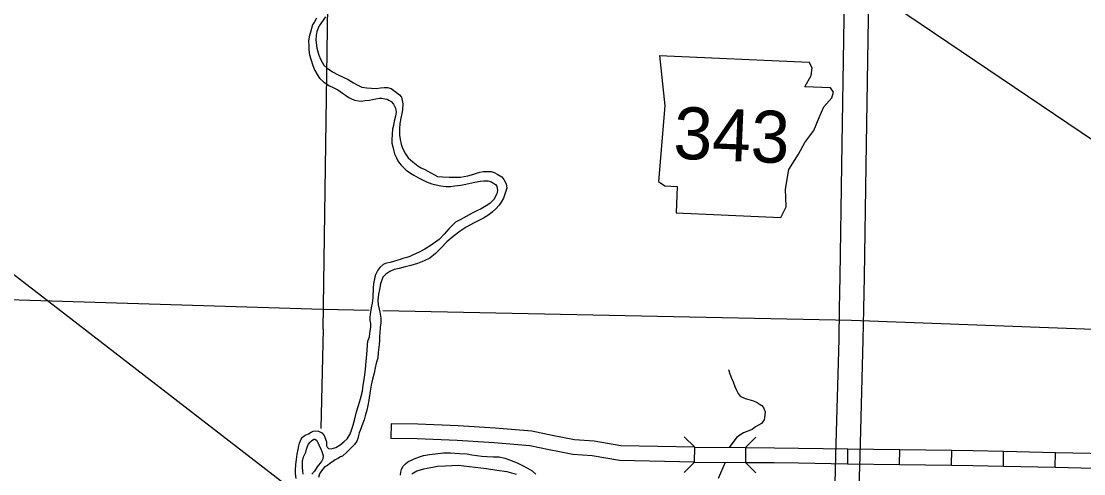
# Model space of a CAD drawing. Extents: x 1196286 to 1268366, y 2040822 to 2082115.
# Drawn here: x 1235560 to 1239613, y 2058686 to 2060409 of the extents above; entities that cross this region are included whole.
import ezdxf

# ---------------------------------------------------------------- set-up
doc = ezdxf.new("R2010")
doc.units = 0
for name, color, linetype in [('60', 7, 'Continuous'), ('61', 7, 'Continuous'), ('62', 7, 'Continuous'), ('Level 69', 7, 'Continuous'), ('Level 72', 7, 'Continuous'), ('Level 78', 7, 'Continuous'), ('Level 8', 7, 'Continuous'), ('Level 83', 7, 'Continuous'), ('Level 87', 7, 'Continuous')]:
    doc.layers.add(name, color=color, linetype=linetype)

msp = doc.modelspace()

# ---------------------------------------------------------------- linework, layer by layer
at = {"layer": '60'}
for points in [[(1236711.8, 2059236.7), (1236740.6, 2061264.4), (1236742.7, 2061422.9)], [(1234763.8, 2059372.9), (1236710.8, 2059312.7), (1236887.6, 2059309.1)], [(1236939.7, 2059308), (1238726.7, 2059270.7), (1239786.4, 2059231.7), (1240836.4, 2059202.8)], [(1236711.8, 2059236.7), (1236702.7, 2058857.5)]]:
    msp.add_lwpolyline(points, dxfattribs=at)
at = {"layer": '61'}
for p, q in [((1238712.6, 2058723.8), (1238713.3, 2058780)), ((1238910.6, 2058721.2), (1238911.3, 2058777.5)), ((1239108.6, 2058718.7), (1239109.3, 2058774.9)), ((1239306.3, 2058715), (1239307.5, 2058771.3)), ((1239504.2, 2058710.7), (1239505.5, 2058766.9))]:
    msp.add_line(p, q, dxfattribs=at)
for points in [[(1238713.3, 2058780), (1238911.3, 2058777.5)], [(1238911.3, 2058777.5), (1239109.3, 2058774.9)], [(1239109.3, 2058774.9), (1239190.8, 2058773.8), (1239307.5, 2058771.3)], [(1239307.5, 2058771.3), (1239505.5, 2058766.9)], [(1239505.5, 2058766.9), (1239703.4, 2058762.5)], [(1238712.6, 2058723.8), (1238910.6, 2058721.2)], [(1238910.6, 2058721.2), (1239108.6, 2058718.7)], [(1239108.6, 2058718.7), (1239189.8, 2058717.6), (1239306.3, 2058715)], [(1239306.3, 2058715), (1239504.2, 2058710.7)], [(1239504.2, 2058710.7), (1239702.2, 2058706.3)]]:
    msp.add_lwpolyline(points, dxfattribs=at)
at = {"layer": '62'}
for points in [[(1236687, 2060421.2), (1236678.6, 2060407.4), (1236671.8, 2060395.4), (1236667.1, 2060381.6), (1236663.6, 2060367.7)], [(1236720.4, 2060426.5), (1236697.2, 2060392.1), (1236692.2, 2060383.2), (1236687.2, 2060370.4), (1236684.8, 2060355.4), (1236684.2, 2060337.7), (1236686.6, 2060317.8), (1236688, 2060306.8), (1236694.8, 2060280.1)], [(1236663.6, 2060367.7), (1236658.9, 2060350), (1236656.5, 2060333.9), (1236657.4, 2060315.8), (1236657.6, 2060300), (1236659.3, 2060281.2), (1236664.3, 2060265), (1236672.3, 2060240.4), (1236680.3, 2060222.3), (1236688.8, 2060206), (1236697.3, 2060193.1), (1236714.3, 2060177.2), (1236735.9, 2060163.8), (1236750.1, 2060156.5), (1236767.6, 2060147.6), (1236785.8, 2060135.4), (1236797.7, 2060127.4), (1236810, 2060118.9), (1236822.3, 2060112.4), (1236832.3, 2060108.9), (1236846.6, 2060106.1), (1236857.4, 2060105.6), (1236870.9, 2060107.4), (1236888.9, 2060109.1), (1236900.2, 2060111.6), (1236913.3, 2060114.1), (1236927.2, 2060116.9), (1236936.2, 2060116.8), (1236947.1, 2060114.5), (1236955.7, 2060112.1), (1236962.8, 2060109), (1236971.7, 2060103.7), (1236980.6, 2060093.8), (1236987.9, 2060077.9), (1236990.7, 2060062.8), (1236987.6, 2060047.4), (1236982.9, 2060029.4), (1236979.7, 2060012.2), (1236976.1, 2059998.3), (1236973.8, 2059959.2), (1236974.4, 2059944.9), (1236977.3, 2059930.9), (1236981.6, 2059915.1), (1236984.5, 2059904.5), (1236991, 2059888.6), (1236996.5, 2059877.7), (1237003.2, 2059868.2), (1237009.1, 2059860.6), (1237018, 2059851.9), (1237029.1, 2059842), (1237045.1, 2059830.5), (1237057.4, 2059822.9), (1237075.3, 2059812.9), (1237090.9, 2059804.8), (1237106.2, 2059797.9), (1237126.7, 2059789.8), (1237142.8, 2059786.6), (1237160.4, 2059783), (1237180.2, 2059780.5), (1237197.1, 2059780), (1237214.3, 2059782.4), (1237237.2, 2059785.6), (1237256, 2059788.7), (1237272.5, 2059793.1), (1237290.9, 2059796.6), (1237311.6, 2059800.2), (1237324.7, 2059801.9), (1237340.5, 2059801), (1237354.6, 2059797.1), (1237368.8, 2059787.5), (1237374.7, 2059781.1), (1237377.1, 2059764.1), (1237374.8, 2059752.1), (1237363.3, 2059730), (1237348.1, 2059714.8), (1237333.8, 2059706.3), (1237314.2, 2059694.4), (1237298, 2059687.5), (1237279.9, 2059678.6), (1237256.9, 2059666.1), (1237233.9, 2059653.5), (1237216.6, 2059644), (1237191.2, 2059618.6), (1237173.7, 2059597.8), (1237154.4, 2059578), (1237123.8, 2059556.9), (1237099.3, 2059541.4), (1237075.1, 2059528.5), (1237055.2, 2059519.3), (1237042.4, 2059513.8), (1237031.5, 2059509.8), (1237015.7, 2059505.1), (1237005.9, 2059501.8), (1236996.1, 2059499.3), (1236979.6, 2059494.2), (1236967.2, 2059490.9), (1236952.9, 2059488.1), (1236941.2, 2059482.9), (1236928.4, 2059471.4), (1236920.4, 2059460.9), (1236909.7, 2059441.1)], [(1236694.8, 2060280.1), (1236701.4, 2060264.9), (1236707.7, 2060253.2), (1236714.7, 2060241.9), (1236726.9, 2060230.4), (1236747.7, 2060217), (1236769, 2060205.9), (1236788.7, 2060197), (1236807, 2060187.1), (1236828.2, 2060175.2), (1236841.6, 2060166.8), (1236859.5, 2060158.7), (1236878.2, 2060155.8), (1236913.8, 2060153.2), (1236930.3, 2060155.3), (1236944.9, 2060157), (1236957.3, 2060157.2), (1236970.7, 2060153.7), (1236991.6, 2060138.4), (1237003.4, 2060128.9), (1237010.1, 2060120.5), (1237013.7, 2060107.3), (1237015.4, 2060094.9), (1237014.4, 2060072.3), (1237012.4, 2060057.7), (1237008.5, 2060039.7), (1237004.9, 2060020.5), (1237003.1, 2059999.9), (1237003.3, 2059975.8), (1237005.3, 2059958.5), (1237009.6, 2059940.7), (1237014.7, 2059926), (1237025.7, 2059904.1), (1237036, 2059889.3), (1237053.5, 2059873.7), (1237073.2, 2059858.4), (1237086.2, 2059851.5), (1237099.6, 2059844.6), (1237148, 2059817.7), (1237166.8, 2059817.2), (1237192.2, 2059816.1), (1237217.3, 2059815.5), (1237235.7, 2059815.3), (1237263.5, 2059820.3), (1237286.4, 2059827.2), (1237296.6, 2059830.4), (1237309.3, 2059834.4), (1237323.6, 2059836.5), (1237352.1, 2059837.7), (1237364.4, 2059833.5), (1237378.6, 2059826.2), (1237393.1, 2059816.6), (1237401.6, 2059807.1), (1237409.7, 2059790.1), (1237412.9, 2059774.2), (1237400.1, 2059734.9), (1237390.9, 2059719.9), (1237383.7, 2059708.7), (1237370.4, 2059694.6), (1237357.9, 2059683.4), (1237343.5, 2059672.3), (1237323.2, 2059659.7), (1237308.4, 2059651.6), (1237287.7, 2059640.9), (1237257.9, 2059624.7), (1237234.9, 2059609.5), (1237207.3, 2059589.5), (1237183.5, 2059568.7), (1237160.7, 2059544.5), (1237141, 2059524.8), (1237119.1, 2059507.3), (1237097.6, 2059496.7), (1237071.7, 2059486.8), (1237046.8, 2059478.4), (1237025.1, 2059473.4), (1237002.1, 2059468), (1236983, 2059463.3), (1236965.7, 2059456.7), (1236950.6, 2059446), (1236939.9, 2059434), (1236930.3, 2059409.3), (1236926.3, 2059387.2), (1236923.1, 2059369.9), (1236920.6, 2059348.5), (1236921.5, 2059329.3), (1236925.1, 2059312.7), (1236927.6, 2059301.7), (1236931.5, 2059278.4), (1236931.6, 2059259.6), (1236928.8, 2059243.8), (1236928.2, 2059221.6), (1236927.4, 2059211.1), (1236926.6, 2059194.9), (1236925.5, 2059178)], [(1236909.7, 2059441.1), (1236906.4, 2059422), (1236904.4, 2059408.8), (1236902, 2059394.6), (1236900.8, 2059355.5), (1236898.8, 2059335.9), (1236896.7, 2059323.9), (1236894, 2059310.4), (1236891.2, 2059292.4), (1236890.3, 2059281.8), (1236890.5, 2059269.4), (1236891.9, 2059258.1), (1236892.9, 2059247.2), (1236891.6, 2059234.8), (1236888.9, 2059221.7), (1236887.2, 2059206.6), (1236882.6, 2059191.8)], [(1236608.4, 2058667), (1236606.2, 2058687), (1236606, 2058699.4), (1236607.2, 2058720.8), (1236609.8, 2058740.3), (1236613.2, 2058760.9), (1236616.2, 2058778.6), (1236619.1, 2058791.7), (1236621.6, 2058802.5), (1236628.6, 2058817.8), (1236632.9, 2058824.5), (1236643.2, 2058832.9), (1236655.6, 2058837.6), (1236665.9, 2058843.8), (1236674.2, 2058847.4), (1236682.1, 2058849.5), (1236693.7, 2058848.1), (1236707, 2058841.4), (1236716.2, 2058831.1), (1236724, 2058807.2), (1236725.2, 2058791.4), (1236727.3, 2058786.9), (1236732.8, 2058781.5), (1236742.2, 2058780.2), (1236759.9, 2058785.5), (1236776.6, 2058795.3), (1236790.7, 2058806.7), (1236803.3, 2058819.2), (1236814.1, 2058835.5), (1236818.1, 2058847.9), (1236826, 2058870.6), (1236832.5, 2058895), (1236839, 2058921.9), (1236846.6, 2058946.2), (1236854.6, 2058971.6), (1236861.6, 2059000.8), (1236864.3, 2059023.4), (1236869, 2059052.2), (1236873, 2059084.1), (1236876.2, 2059113.4), (1236879, 2059140.4), (1236882.6, 2059191.8)], [(1236925.5, 2059178), (1236921.9, 2059147.2), (1236920.3, 2059126.4), (1236914.3, 2059107), (1236910.2, 2059088.6), (1236906, 2059068.8), (1236900.7, 2059046.3), (1236895, 2059023.1), (1236891.6, 2059000.6), (1236886, 2058965.4), (1236882.2, 2058945.5), (1236878.1, 2058927.9), (1236872.1, 2058906.6), (1236868, 2058890.9), (1236863.3, 2058878.5), (1236858.2, 2058864.7), (1236852.6, 2058850.5), (1236848.7, 2058841.6), (1236846.6, 2058831.1), (1236843.8, 2058820.3), (1236840.2, 2058809.8), (1236831.7, 2058797.2), (1236814.5, 2058780.2), (1236802.3, 2058768.4), (1236785.1, 2058753), (1236777.6, 2058750.5), (1236768.1, 2058744.3), (1236757.8, 2058738.1), (1236748, 2058731.5), (1236737.7, 2058724.6), (1236728.6, 2058717.2), (1236726.3, 2058715.8), (1236720.2, 2058712.9), (1236716, 2058709.6), (1236705.3, 2058697), (1236698.3, 2058685.9), (1236693.6, 2058671.3)], [(1238258.1, 2059082.3), (1238263.1, 2059066), (1238269.5, 2059049.7), (1238276.3, 2059035.3), (1238281.6, 2059018.2), (1238288.1, 2059003.8), (1238294.6, 2058990.9), (1238302.2, 2058981), (1238321.2, 2058971.9), (1238336.1, 2058969), (1238353.3, 2058963.8), (1238367, 2058956.7), (1238378.8, 2058950.1), (1238385.1, 2058945.8), (1238392.1, 2058938.5), (1238394.6, 2058930.6), (1238397.4, 2058922.6), (1238396.4, 2058908.7), (1238394.2, 2058891.1), (1238383.5, 2058877.7), (1238361.2, 2058865), (1238348.1, 2058854.2), (1238315.3, 2058841.3), (1238289.4, 2058825), (1238259.9, 2058785.6)], [(1236645.7, 2058767.7), (1236648.5, 2058779.4), (1236655.2, 2058797.3), (1236661.7, 2058805.5), (1236667.5, 2058811.4), (1236676.6, 2058817.2), (1236680.3, 2058817.5), (1236686.6, 2058813.3), (1236692.4, 2058802.2), (1236698.1, 2058789.3), (1236702.5, 2058781), (1236707.1, 2058770.7), (1236709.6, 2058762.8), (1236711.3, 2058754.1), (1236710.7, 2058742.8), (1236706, 2058732.4), (1236689.5, 2058712.4), (1236678.7, 2058696), (1236668.7, 2058683.5)], [(1236635.7, 2058684.5), (1236634.1, 2058696.9), (1236633.2, 2058708.2), (1236633.1, 2058719.9), (1236633.7, 2058734.2), (1236637.3, 2058750.7), (1236645.7, 2058767.7)], [(1237006.7, 2058680.1), (1237008.4, 2058692.1), (1237010.5, 2058701.4), (1237016, 2058713.7), (1237025.5, 2058723.3), (1237035.4, 2058730.6), (1237059.6, 2058743), (1237079.3, 2058750.5), (1237095.1, 2058755.8), (1237117.7, 2058758.7), (1237170.3, 2058765.6), (1237197.2, 2058765), (1237232.4, 2058762.8), (1237261.6, 2058761.8), (1237278.4, 2058758.1), (1237317.3, 2058752.8), (1237337.9, 2058751.3), (1237360.7, 2058750.5), (1237383.2, 2058749.6), (1237405.2, 2058745), (1237426.8, 2058737.5), (1237454.3, 2058726.4), (1237472.5, 2058717.7), (1237491.4, 2058706.8), (1237508.8, 2058697.1), (1237523.6, 2058684.7)], [(1237449, 2058682.5), (1237414.3, 2058693), (1237374.3, 2058697.9), (1237335.1, 2058704.7), (1237227.4, 2058717), (1237179, 2058715), (1237147.5, 2058713), (1237123, 2058708.2), (1237095.2, 2058703.5), (1237068.8, 2058696.1), (1237049.9, 2058684.5)], [(1238245.7, 2058728.3), (1238218.5, 2058667.8)]]:
    msp.add_lwpolyline(points, dxfattribs=at)
at = {"layer": 'Level 69'}
for p, q in [((1238128.6, 2058730.2), (1238129, 2058786.5)), ((1238322.7, 2058785.4), (1238322.4, 2058729.1))]:
    msp.add_line(p, q, dxfattribs=at)
for points in [[(1238129, 2058786.5), (1238327, 2058785.2)], [(1238327, 2058785.2), (1238433.4, 2058784.5), (1238525.3, 2058783)], [(1238525.3, 2058783), (1238713.4, 2058780)], [(1238128.6, 2058730.2), (1238326.6, 2058729)], [(1238326.6, 2058729), (1238432.8, 2058728.3), (1238524.4, 2058726.8)], [(1238524.4, 2058726.8), (1238712.5, 2058723.8)]]:
    msp.add_lwpolyline(points, dxfattribs=at)
at = {"layer": 'Level 72'}
for points in [[(1236970.8, 2058876.3), (1236970.1, 2058820.1)], [(1238129.4, 2058786.5), (1237847.3, 2058791.8), (1237745.4, 2058810.3), (1237670.6, 2058815.3), (1237624.6, 2058823.8), (1237585.5, 2058831.8), (1237507.8, 2058847.3), (1237368.2, 2058859.3), (1237226.6, 2058868.3), (1237072.6, 2058874.9), (1236970.8, 2058876.3)], [(1238128.3, 2058730.2), (1237841.7, 2058735.6), (1237738.4, 2058754.4), (1237663.6, 2058759.4), (1237613.9, 2058768.6), (1237574.4, 2058776.6), (1237499.9, 2058791.5), (1237364, 2058803.2), (1237223.6, 2058812.2), (1237071, 2058818.7), (1236970.1, 2058820.1)]]:
    msp.add_lwpolyline(points, dxfattribs=at)
at = {"layer": 'Level 78'}
for p, q in [((1237995.1, 2060278.7), (1238015.5, 2060087.4)), ((1238577.3, 2060231.6), (1238565.1, 2060254)), ((1238572.9, 2060203.2), (1238577.3, 2060231.6)), ((1238548.8, 2060159.8), (1238572.9, 2060203.2)), ((1238647.1, 2060155.6), (1238548.8, 2060159.8)), ((1238659, 2060139.2), (1238647.1, 2060155.6)), ((1238651.8, 2060117.3), (1238659, 2060139.2)), ((1238621.7, 2060083.6), (1238651.8, 2060117.3)), ((1238015.5, 2060087.4), (1237990.4, 2059799.5)), ((1238604.1, 2060043.1), (1238621.7, 2060083.6)), ((1238582.9, 2059993.2), (1238604.1, 2060043.1)), ((1238549.2, 2059947), (1238582.9, 2059993.2)), ((1238525.1, 2059903.6), (1238549.2, 2059947)), ((1238487.7, 2059844.9), (1238525.1, 2059903.6)), ((1238474.9, 2059769.2), (1238487.7, 2059844.9)), ((1237990.4, 2059799.5), (1238015.1, 2059782.6)), ((1238015.1, 2059782.6), (1238062.7, 2059780.5)), ((1238062.7, 2059780.5), (1238058.3, 2059679.1)), ((1238478.4, 2059702.4), (1238474.9, 2059769.2)), ((1238457.6, 2059662), (1238478.4, 2059702.4)), ((1238058.3, 2059679.1), (1238457.6, 2059662))]:
    msp.add_line(p, q, dxfattribs=at)
msp.add_lwpolyline([(1237995.1, 2060278.7), (1238565.1, 2060254)], dxfattribs=at)
at = {"layer": 'Level 8'}
for p, q in [((1243606.9, 2057283.5), (1236659.6, 2061971.8)), ((1244055.7, 2052875.3), (1234478.1, 2060255.6))]:
    msp.add_line(p, q, dxfattribs=at)
at = {"layer": 'Level 83'}
for points in [[(1238089.5, 2058826.5), (1238129, 2058786.5)], [(1238322.7, 2058785.4), (1238362.8, 2058824.9)], [(1238128.6, 2058730.2), (1238088.6, 2058690.7)], [(1238361.9, 2058689.1), (1238322.4, 2058729.1)]]:
    msp.add_lwpolyline(points, dxfattribs=at)
at = {"layer": 'Level 87'}
for p, q in [((1238700.3, 2060552.4), (1238689.3, 2059861.7)), ((1238783, 2059860.2), (1238794, 2060550.9)), ((1238689.3, 2059861.7), (1238682.5, 2059437.5)), ((1238776.3, 2059436), (1238783, 2059860.2)), ((1238682.5, 2059437.5), (1238680.6, 2059314.3)), ((1238774.3, 2059312.7), (1238776.3, 2059436)), ((1238680.6, 2059314.3), (1238678.3, 2059198.3)), ((1238772, 2059196.1), (1238774.3, 2059312.7)), ((1238678.3, 2059198.3), (1238666.2, 2058754.7)), ((1238759.9, 2058752.1), (1238772, 2059196.1)), ((1238666.2, 2058754.7), (1238622.8, 2057203)), ((1238716.5, 2057200.7), (1238759.9, 2058752.1))]:
    msp.add_line(p, q, dxfattribs=at)

# ---------------------------------------------------------------- texts
at = {"layer": 'Level 78'}
msp.add_text('343', height=198, rotation=357.548, dxfattribs=at).set_placement((1238045.6, 2059886.5))

doc.saveas('drawing.dxf')
